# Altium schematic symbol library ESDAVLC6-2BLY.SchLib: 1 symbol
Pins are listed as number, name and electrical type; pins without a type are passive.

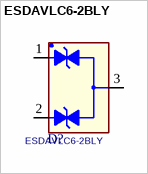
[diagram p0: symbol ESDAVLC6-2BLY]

## ESDAVLC6-2BLY
designator D?
footprint ST_SOT23-3L
pins: 1 K1, 2 K2, 3 A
